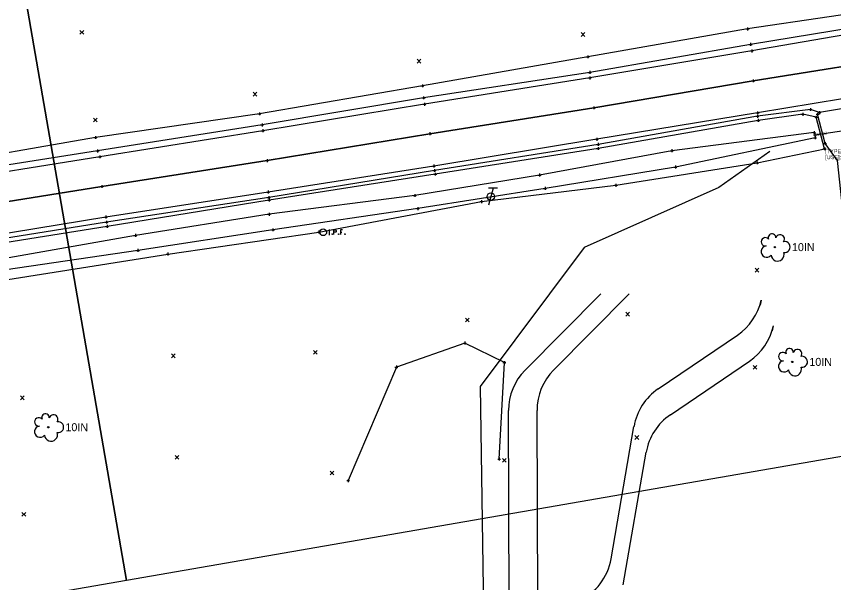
# Model space of a CAD drawing. Extents: x 1386013 to 1389776, y 604170 to 607009.
# Drawn here: x 1386684 to 1386970, y 604555.1 to 604753.1 of the extents above; entities that cross this region are included whole.
import ezdxf

# ---------------------------------------------------------------- set-up
doc = ezdxf.new("R2010")
doc.units = 0
for name, color, linetype in [('_CIVIL_CONSTRUCTION', 7, 'Continuous'), ('DR_X_Storm_Sewer', 7, 'Continuous'), ('DV_X_Text', 7, 'Continuous'), ('PM_X_CL_Double_Solid', 7, 'Continuous'), ('PV_X_COP', 7, 'Continuous'), ('PV_X_Driveway', 7, 'Continuous'), ('PV_X_EOP', 7, 'Continuous'), ('PV_X_Shoulder', 7, 'Continuous'), ('SC_Scratch1', 7, 'Continuous'), ('SH_Cut_Line', 7, 'Continuous'), ('SV_X_Random_Point', 7, 'Continuous'), ('SV_X_Text', 7, 'Continuous'), ('SV_X_Toe_of_Slope', 7, 'Continuous'), ('SV_X_Top_of_Bank', 7, 'Continuous'), ('UT_X_Leach_Bed', 7, 'Continuous'), ('UT_X_Telecom_Cells', 7, 'Continuous'), ('VG_X_Text', 7, 'Continuous'), ('VG_X_Tree_Line_Rt', 7, 'Continuous')]:
    doc.layers.add(name, color=color, linetype=linetype)

msp = doc.modelspace()

# ---------------------------------------------------------------- linework, layer by layer
at = {"layer": '_CIVIL_CONSTRUCTION'}
for centre in [(1386949.46, 604672.43), (1386955.54, 604632.3), (1386695.17, 604609.45)]:
    msp.add_circle(centre, 0.24, dxfattribs=at)
for centre, radius, start, end in [((1386946.15, 604674.29), 1.47, 39.0625, 279.5412), ((1386948.48, 604675.79), 1.32, 354.0047, 205.9741), ((1386951.29, 604675.25), 1.55, 323.83, 165.0376), ((1386946.61, 604670.88), 1.97, 96.1722, 320.5737), ((1386952.92, 604672.46), 1.91, 259.1453, 101.4596), ((1386950.41, 604669.82), 2.28, 184.9476, 19.4572), ((1386952.23, 604634.16), 1.47, 39.0625, 279.5412), ((1386954.56, 604635.67), 1.32, 354.0047, 205.9741), ((1386957.37, 604635.13), 1.55, 323.83, 165.0376), ((1386952.69, 604630.75), 1.97, 96.1722, 320.5737), ((1386959, 604632.34), 1.91, 259.1453, 101.4596), ((1386956.49, 604629.69), 2.28, 184.9476, 19.4572), ((1386691.86, 604611.31), 1.47, 39.0625, 279.5412), ((1386694.19, 604612.82), 1.32, 354.0047, 205.9741), ((1386697, 604612.28), 1.55, 323.83, 165.0376), ((1386692.32, 604607.9), 1.97, 96.1722, 320.5737), ((1386698.63, 604609.48), 1.91, 259.1453, 101.4596), ((1386696.12, 604606.84), 2.28, 184.9476, 19.4572)]:
    msp.add_arc(centre, radius, start, end, dxfattribs=at)
at = {"layer": 'DR_X_Storm_Sewer'}
msp.add_line((1386963.45, 604711.66), (1386994.09, 604716.38), dxfattribs=at)
msp.add_lwpolyline([(1386947.76, 604705.84), (1386929.86, 604693.24), (1386882.71, 604672.27), (1386846.3, 604623.65), (1386848.33, 604490.41), (1386873.09, 604380.23)], dxfattribs=at)
at = {"layer": 'DV_X_Text'}
for p, q in [((1386939.93, 604749.23), (1386939.93, 604748.23)), ((1386939.43, 604748.73), (1386940.43, 604748.73)), ((1386939.93, 604748.73), (1386939.93, 604748.73)), ((1386940.47, 604743.32), (1386941.47, 604743.32)), ((1386940.97, 604743.82), (1386940.97, 604742.82)), ((1386940.97, 604743.32), (1386940.97, 604743.32)), ((1386940.91, 604741.04), (1386941.91, 604741.04)), ((1386941.41, 604741.54), (1386941.41, 604740.54)), ((1386941.41, 604741.04), (1386941.41, 604741.04)), ((1386883.48, 604739), (1386884.48, 604739)), ((1386883.98, 604739.5), (1386883.98, 604738.5)), ((1386883.98, 604739), (1386883.98, 604739)), ((1386884.15, 604733.55), (1386885.15, 604733.55)), ((1386884.65, 604734.05), (1386884.65, 604733.05)), ((1386884.65, 604733.55), (1386884.65, 604733.55)), ((1386884.67, 604732.09), (1386884.67, 604731.09)), ((1386825.59, 604728.82), (1386826.59, 604728.82)), ((1386826.09, 604729.32), (1386826.09, 604728.32)), ((1386826.09, 604728.82), (1386826.09, 604728.82)), ((1386884.17, 604731.59), (1386885.17, 604731.59)), ((1386884.67, 604731.59), (1386884.67, 604731.59)), ((1386941.42, 604730.57), (1386942.42, 604730.57)), ((1386941.92, 604731.07), (1386941.92, 604730.07)), ((1386941.92, 604730.57), (1386941.92, 604730.57)), ((1386826.04, 604724.64), (1386827.04, 604724.64)), ((1386826.54, 604725.14), (1386826.54, 604724.14)), ((1386826.54, 604724.64), (1386826.54, 604724.64)), ((1386826.32, 604722.39), (1386827.32, 604722.39)), ((1386826.82, 604722.89), (1386826.82, 604721.89)), ((1386826.82, 604722.39), (1386826.82, 604722.39)), ((1386885.6, 604721.12), (1386886.6, 604721.12)), ((1386886.1, 604721.62), (1386886.1, 604720.62)), ((1386886.1, 604721.12), (1386886.1, 604721.12)), ((1386961.4, 604720.55), (1386962.4, 604720.55)), ((1386961.9, 604721.05), (1386961.9, 604720.05)), ((1386961.9, 604720.55), (1386961.9, 604720.55)), ((1386768.54, 604719.03), (1386769.54, 604719.03)), ((1386769.04, 604719.53), (1386769.04, 604718.53)), ((1386769.04, 604719.03), (1386769.04, 604719.03)), ((1386942.88, 604718.17), (1386943.88, 604718.17)), ((1386942.92, 604719.4), (1386943.92, 604719.4)), ((1386943.38, 604718.67), (1386943.38, 604717.67)), ((1386943.38, 604718.17), (1386943.38, 604718.17)), ((1386943.42, 604719.9), (1386943.42, 604718.9)), ((1386943.42, 604719.4), (1386943.42, 604719.4)), ((1386958.71, 604718.9), (1386959.71, 604718.9)), ((1386959.21, 604719.4), (1386959.21, 604718.4)), ((1386959.21, 604718.9), (1386959.21, 604718.9)), ((1386963.45, 604717.89), (1386964.45, 604717.89)), ((1386963.92, 604718.9), (1386964.92, 604718.9)), ((1386963.95, 604718.39), (1386963.95, 604717.39)), ((1386963.95, 604717.89), (1386963.95, 604717.89)), ((1386964.42, 604719.4), (1386964.42, 604718.4)), ((1386964.42, 604718.9), (1386964.42, 604718.9)), ((1386964.61, 604719.46), (1386965.61, 604719.46)), ((1386965.11, 604719.96), (1386965.11, 604718.96)), ((1386965.11, 604719.46), (1386965.11, 604719.46)), ((1386769.48, 604715.15), (1386770.48, 604715.15)), ((1386769.98, 604715.65), (1386769.98, 604714.65)), ((1386769.98, 604715.15), (1386769.98, 604715.15)), ((1386943.17, 604716.74), (1386944.17, 604716.74)), ((1386943.67, 604717.24), (1386943.67, 604716.24)), ((1386943.67, 604716.74), (1386943.67, 604716.74)), ((1386769.7, 604713.13), (1386770.7, 604713.13)), ((1386770.2, 604713.63), (1386770.2, 604712.63)), ((1386770.2, 604713.13), (1386770.2, 604713.13)), ((1386828.25, 604712.1), (1386829.25, 604712.1)), ((1386828.75, 604712.6), (1386828.75, 604711.6)), ((1386828.75, 604712.1), (1386828.75, 604712.1)), ((1386962.7, 604712.53), (1386963.7, 604712.53)), ((1386962.95, 604711.66), (1386963.95, 604711.66)), ((1386963.2, 604713.03), (1386963.2, 604712.03)), ((1386963.2, 604712.53), (1386963.2, 604712.53)), ((1386963.45, 604712.16), (1386963.45, 604711.16)), ((1386963.45, 604711.66), (1386963.45, 604711.66)), ((1386711.2, 604710.77), (1386712.2, 604710.77)), ((1386711.7, 604711.27), (1386711.7, 604710.27)), ((1386711.7, 604710.77), (1386711.7, 604710.77)), ((1386886.64, 604710.13), (1386887.64, 604710.13)), ((1386887.14, 604710.63), (1386887.14, 604709.63)), ((1386887.14, 604710.13), (1386887.14, 604710.13)), ((1386887.62, 604708.86), (1386887.62, 604707.86)), ((1386963.06, 604710.65), (1386964.06, 604710.65)), ((1386963.56, 604711.15), (1386963.56, 604710.15)), ((1386963.56, 604710.65), (1386963.56, 604710.65)), ((1386967.09, 604709.18), (1386967.09, 604708.18)), ((1386711.92, 604706.07), (1386712.92, 604706.07)), ((1386712.42, 604706.57), (1386712.42, 604705.57)), ((1386712.42, 604706.07), (1386712.42, 604706.07)), ((1386887.08, 604706.91), (1386888.08, 604706.91)), ((1386887.12, 604708.36), (1386888.12, 604708.36)), ((1386887.58, 604707.41), (1386887.58, 604706.41)), ((1386887.58, 604706.91), (1386887.58, 604706.91)), ((1386887.62, 604708.36), (1386887.62, 604708.36)), ((1386912.92, 604706.16), (1386913.92, 604706.16)), ((1386913.42, 604706.66), (1386913.42, 604705.66)), ((1386913.42, 604706.16), (1386913.42, 604706.16)), ((1386966.3, 604706.78), (1386967.3, 604706.78)), ((1386966.45, 604706.82), (1386967.45, 604706.82)), ((1386966.59, 604708.68), (1386967.59, 604708.68)), ((1386966.8, 604707.28), (1386966.8, 604706.28)), ((1386966.8, 604706.78), (1386966.8, 604706.78)), ((1386966.95, 604707.32), (1386966.95, 604706.32)), ((1386966.95, 604706.82), (1386966.95, 604706.82)), ((1386967.09, 604708.68), (1386967.09, 604708.68)), ((1386712.65, 604704.01), (1386713.65, 604704.01)), ((1386713.15, 604704.51), (1386713.15, 604703.51)), ((1386713.15, 604704.01), (1386713.15, 604704.01)), ((1386771.72, 604703.17), (1386771.72, 604702.17)), ((1386771.22, 604702.67), (1386772.22, 604702.67)), ((1386771.72, 604702.67), (1386771.72, 604702.67)), ((1386829.62, 604700.78), (1386830.62, 604700.78)), ((1386830.12, 604701.28), (1386830.12, 604700.28)), ((1386830.12, 604700.78), (1386830.12, 604700.78)), ((1386914.19, 604700.42), (1386915.19, 604700.42)), ((1386914.69, 604700.92), (1386914.69, 604699.92)), ((1386914.69, 604700.42), (1386914.69, 604700.42)), ((1386942.8, 604701.92), (1386943.8, 604701.92)), ((1386943.3, 604702.42), (1386943.3, 604701.42)), ((1386943.3, 604701.92), (1386943.3, 604701.92)), ((1386829.86, 604699.21), (1386830.86, 604699.21)), ((1386830.11, 604697.95), (1386831.11, 604697.95)), ((1386830.36, 604699.71), (1386830.36, 604698.71)), ((1386830.36, 604699.21), (1386830.36, 604699.21)), ((1386830.61, 604698.45), (1386830.61, 604697.45)), ((1386830.61, 604697.95), (1386830.61, 604697.95)), ((1386866.62, 604697.62), (1386867.62, 604697.62)), ((1386867.12, 604698.12), (1386867.12, 604697.12)), ((1386867.12, 604697.62), (1386867.12, 604697.62)), ((1386893.85, 604694.55), (1386893.85, 604693.55)), ((1386713.35, 604693.61), (1386714.35, 604693.61)), ((1386713.85, 604694.11), (1386713.85, 604693.11)), ((1386713.85, 604693.61), (1386713.85, 604693.61)), ((1386771.6, 604691.69), (1386772.6, 604691.69)), ((1386772.1, 604692.19), (1386772.1, 604691.19)), ((1386772.1, 604691.69), (1386772.1, 604691.69)), ((1386868.52, 604692.96), (1386869.52, 604692.96)), ((1386869.02, 604693.46), (1386869.02, 604692.46)), ((1386869.02, 604692.96), (1386869.02, 604692.96)), ((1386893.35, 604694.05), (1386894.35, 604694.05)), ((1386893.85, 604694.05), (1386893.85, 604694.05)), ((1386771.8, 604689.74), (1386772.8, 604689.74)), ((1386771.95, 604688.91), (1386772.95, 604688.91)), ((1386772.3, 604690.24), (1386772.3, 604689.24)), ((1386772.3, 604689.74), (1386772.3, 604689.74)), ((1386772.45, 604689.41), (1386772.45, 604688.41)), ((1386772.45, 604688.91), (1386772.45, 604688.91)), ((1386822.92, 604690.47), (1386823.92, 604690.47)), ((1386823.42, 604690.97), (1386823.42, 604689.97)), ((1386823.42, 604690.47), (1386823.42, 604690.47)), ((1386846.74, 604688.83), (1386846.74, 604687.83)), ((1386824, 604685.91), (1386825, 604685.91)), ((1386824.5, 604686.41), (1386824.5, 604685.41)), ((1386824.5, 604685.91), (1386824.5, 604685.91)), ((1386846.24, 604688.33), (1386847.24, 604688.33)), ((1386846.74, 604688.33), (1386846.74, 604688.33)), ((1386715.3, 604683.44), (1386715.3, 604682.44)), ((1386771.94, 604683.92), (1386772.94, 604683.92)), ((1386772.44, 604684.42), (1386772.44, 604683.42)), ((1386772.44, 604683.92), (1386772.44, 604683.92)), ((1386714.8, 604682.94), (1386715.8, 604682.94)), ((1386715.06, 604681.18), (1386716.06, 604681.18)), ((1386715.3, 604682.94), (1386715.3, 604682.94)), ((1386715.56, 604681.68), (1386715.56, 604680.68)), ((1386715.56, 604681.18), (1386715.56, 604681.18)), ((1386715.75, 604680.2), (1386715.75, 604679.2)), ((1386715.25, 604679.7), (1386716.25, 604679.7)), ((1386715.75, 604679.7), (1386715.75, 604679.7)), ((1386773.31, 604678.46), (1386774.31, 604678.46)), ((1386773.81, 604678.96), (1386773.81, 604677.96)), ((1386773.81, 604678.46), (1386773.81, 604678.46)), ((1386789.41, 604677.7), (1386790.41, 604677.7)), ((1386789.91, 604678.2), (1386789.91, 604677.2)), ((1386789.91, 604677.7), (1386789.91, 604677.7)), ((1386725.14, 604676.53), (1386726.14, 604676.53)), ((1386725.64, 604677.03), (1386725.64, 604676.03)), ((1386725.64, 604676.53), (1386725.64, 604676.53)), ((1386726.54, 604671.79), (1386726.54, 604670.79)), ((1386726.04, 604671.29), (1386727.04, 604671.29)), ((1386726.54, 604671.29), (1386726.54, 604671.29)), ((1386736.47, 604670), (1386737.47, 604670)), ((1386736.97, 604670.5), (1386736.97, 604669.5)), ((1386736.97, 604670), (1386736.97, 604670)), ((1386840.47, 604638.87), (1386841.47, 604638.87)), ((1386840.97, 604639.37), (1386840.97, 604638.37)), ((1386840.97, 604638.87), (1386840.97, 604638.87)), ((1386854.3, 604632.1), (1386855.3, 604632.1)), ((1386854.8, 604632.6), (1386854.8, 604631.6)), ((1386854.8, 604632.1), (1386854.8, 604632.1)), ((1386816.49, 604630.49), (1386817.49, 604630.49)), ((1386816.99, 604630.99), (1386816.99, 604629.99)), ((1386816.99, 604630.49), (1386816.99, 604630.49)), ((1386852.49, 604598.32), (1386853.49, 604598.32)), ((1386852.99, 604598.82), (1386852.99, 604597.82)), ((1386852.99, 604598.32), (1386852.99, 604598.32)), ((1386799.64, 604590.78), (1386800.64, 604590.78)), ((1386800.14, 604591.28), (1386800.14, 604590.28)), ((1386800.14, 604590.78), (1386800.14, 604590.78))]:
    msp.add_line(p, q, dxfattribs=at)
at = {"layer": 'PM_X_CL_Double_Solid'}
msp.add_lwpolyline([(1386468.73, 604654.2), (1386537.3, 604664.92), (1386594.48, 604674.79), (1386656.33, 604684.46), (1386713.85, 604693.61), (1386771.72, 604702.67), (1386828.75, 604712.1), (1386886.1, 604721.12), (1386941.92, 604730.57), (1387000.37, 604739.9)], dxfattribs=at)
at = {"layer": 'PV_X_COP'}
msp.add_lwpolyline([(1387000.37, 604739.9), (1386941.92, 604730.57), (1386886.1, 604721.12), (1386828.75, 604712.1), (1386771.72, 604702.67), (1386713.85, 604693.61), (1386656.33, 604684.46), (1386594.48, 604674.79), (1386537.3, 604664.92), (1386475.24, 604654.93), (1386414.35, 604644.79), (1386366.58, 604636.8), (1386295.22, 604625.24), (1386269.2, 604620.76)], dxfattribs=at)
at = {"layer": 'PV_X_Driveway'}
msp.add_lwpolyline([(1386976.17, 604633.16), (1386974.25, 604675.51), (1386971.44, 604702.7), (1386967.09, 604708.68), (1386964.42, 604718.9)], dxfattribs=at)
at = {"layer": 'PV_X_EOP'}
for points in [[(1386999.09, 604750.97), (1386941.41, 604741.04), (1386884.67, 604731.59), (1386826.82, 604722.39), (1386770.2, 604713.13), (1386713.15, 604704.01), (1386654.93, 604694.71), (1386593.34, 604684.8), (1386535.41, 604675.21), (1386469.16, 604664.5), (1386392.09, 604651.62), (1386332.26, 604641.82), (1386267.39, 604631.1)], [(1387002.9, 604729.17), (1386943.42, 604719.4), (1386887.14, 604710.13), (1386830.12, 604700.78), (1386772.1, 604691.69), (1386715.3, 604682.94), (1386657.65, 604673.44), (1386596.41, 604663.71), (1386538.98, 604654.04), (1386477.51, 604644.07), (1386414.44, 604633.64), (1386368.83, 604626.04), (1386296.84, 604614.17), (1386270.69, 604609.87)]]:
    msp.add_lwpolyline(points, dxfattribs=at)
at = {"layer": 'PV_X_Shoulder'}
for points in [[(1386998.59, 604752.7), (1386940.97, 604743.32), (1386884.65, 604733.55), (1386826.54, 604724.64), (1386769.98, 604715.15), (1386712.42, 604706.07), (1386654.65, 604697.02), (1386593.22, 604686.44), (1386535.13, 604677.03), (1386468.95, 604665.92), (1386392.3, 604653.36), (1386331.76, 604643.52), (1386267.19, 604632.89)], [(1386985.4, 604722.84), (1386965.11, 604719.46), (1386961.9, 604720.55), (1386943.38, 604718.17), (1386887.62, 604708.36), (1386830.36, 604699.21), (1386772.3, 604689.74), (1386715.56, 604681.18), (1386657.89, 604671.95), (1386596.66, 604661.6), (1386577.12, 604657.52), (1386569.07, 604656.76), (1386539.67, 604652.01), (1386479.08, 604642.34), (1386478.07, 604642.14), (1386414.53, 604632.43), (1386369.38, 604624.9), (1386296.82, 604613.19), (1386270.73, 604608.85)]]:
    msp.add_lwpolyline(points, dxfattribs=at)
at = {"layer": 'SC_Scratch1'}
for points in [[(1386793.4, 604678.44), (1386793.75, 604678.44)], [(1386793.57, 604676.84), (1386793.57, 604678.44)], [(1386795.14, 604676.84), (1386795.14, 604678.44), (1386795.67, 604678.44), (1386795.72, 604678.43), (1386795.8, 604678.4), (1386795.83, 604678.38), (1386795.86, 604678.35), (1386795.91, 604678.29), (1386795.94, 604678.22), (1386795.96, 604678.12), (1386795.96, 604677.97), (1386795.95, 604677.92), (1386795.93, 604677.85), (1386795.89, 604677.76), (1386795.84, 604677.72), (1386795.81, 604677.69), (1386795.75, 604677.67), (1386795.67, 604677.66), (1386795.14, 604677.66)], [(1386798.15, 604678.44), (1386797.39, 604678.44), (1386797.39, 604676.84)], [(1386797.39, 604677.66), (1386797.93, 604677.66)], [(1386793.4, 604676.84), (1386793.75, 604676.84)], [(1386794.53, 604677.05), (1386794.59, 604677.05), (1386794.62, 604677.03), (1386794.65, 604676.98), (1386794.65, 604676.91), (1386794.62, 604676.86), (1386794.59, 604676.84), (1386794.53, 604676.84), (1386794.5, 604676.86), (1386794.46, 604676.91), (1386794.46, 604676.98), (1386794.5, 604677.03), (1386794.53, 604677.05)], [(1386796.78, 604677.05), (1386796.83, 604677.05), (1386796.87, 604677.03), (1386796.9, 604676.98), (1386796.9, 604676.91), (1386796.87, 604676.86), (1386796.83, 604676.84), (1386796.78, 604676.84), (1386796.75, 604676.86), (1386796.71, 604676.91), (1386796.71, 604676.98), (1386796.75, 604677.03), (1386796.78, 604677.05)], [(1386798.93, 604677.05), (1386798.98, 604677.05), (1386799.02, 604677.03), (1386799.05, 604676.98), (1386799.05, 604676.91), (1386799.02, 604676.86), (1386798.98, 604676.84), (1386798.93, 604676.84), (1386798.9, 604676.86), (1386798.86, 604676.91), (1386798.86, 604676.98), (1386798.9, 604677.03), (1386798.93, 604677.05)]]:
    msp.add_lwpolyline(points, dxfattribs=at)
msp.add_circle((1386791.38, 604677.64), 1.2, dxfattribs=at)
at = {"layer": 'SH_Cut_Line'}
for points in [[(1386722.57, 604555.82), (1386685.02, 604772.59), (1387020.03, 604830.63), (1387057.58, 604613.85)], [(1386387.56, 604497.79), (1386350, 604714.56), (1386685.02, 604772.59), (1386722.57, 604555.82)]]:
    msp.add_lwpolyline(points, close=True, dxfattribs=at)
at = {"layer": 'SV_X_Random_Point'}
for p, q in [((1386706.26, 604746.88), (1386707.59, 604748.22)), ((1386706.26, 604748.22), (1386707.59, 604746.88)), ((1386881.67, 604746.09), (1386883, 604747.43)), ((1386881.67, 604747.43), (1386883, 604746.09)), ((1386824.23, 604736.82), (1386825.57, 604738.15)), ((1386824.23, 604738.15), (1386825.57, 604736.82)), ((1386766.88, 604725.27), (1386768.21, 604726.6)), ((1386766.88, 604726.6), (1386768.21, 604725.27)), ((1386710.95, 604716.23), (1386712.28, 604717.56)), ((1386710.95, 604717.56), (1386712.28, 604716.23)), ((1386942.58, 604663.73), (1386943.91, 604665.06)), ((1386942.58, 604665.06), (1386943.91, 604663.73)), ((1386897.28, 604648.31), (1386898.61, 604649.64)), ((1386897.28, 604649.64), (1386898.61, 604648.31)), ((1386841.17, 604646.31), (1386842.5, 604647.64)), ((1386841.17, 604647.64), (1386842.5, 604646.31)), ((1386738.3, 604633.77), (1386739.63, 604635.1)), ((1386738.3, 604635.1), (1386739.63, 604633.77)), ((1386787.94, 604635), (1386789.27, 604636.33)), ((1386787.94, 604636.33), (1386789.27, 604635)), ((1386941.82, 604629.74), (1386943.15, 604631.08)), ((1386941.82, 604631.08), (1386943.15, 604629.74)), ((1386685.44, 604619.05), (1386686.77, 604620.39)), ((1386685.44, 604620.39), (1386686.77, 604619.05)), ((1386900.47, 604605.19), (1386901.8, 604606.53)), ((1386900.47, 604606.53), (1386901.8, 604605.19)), ((1386739.58, 604598.25), (1386740.91, 604599.58)), ((1386739.58, 604599.58), (1386740.91, 604598.25)), ((1386854.1, 604597.19), (1386855.43, 604598.53)), ((1386854.1, 604598.53), (1386855.43, 604597.19)), ((1386793.78, 604592.79), (1386795.11, 604594.12)), ((1386793.78, 604594.12), (1386795.11, 604592.79)), ((1386685.93, 604578.32), (1386687.26, 604579.65)), ((1386685.93, 604579.65), (1386687.26, 604578.32))]:
    msp.add_line(p, q, dxfattribs=at)
at = {"layer": 'SV_X_Toe_of_Slope'}
for points in [[(1387571.9, 604860.13), (1387513.17, 604847.9), (1387455.73, 604837.69), (1387401.04, 604827.65), (1387339.29, 604815.83), (1387289.1, 604807.74), (1387230.03, 604798.15), (1387173.08, 604787.71), (1387123.84, 604780.19), (1387058.58, 604768.72), (1386997.09, 604757.11), (1386939.93, 604748.73), (1386883.98, 604739), (1386826.09, 604728.82), (1386769.04, 604719.03), (1386711.7, 604710.77), (1386654.03, 604700.72), (1386592.6, 604690.63), (1386534.1, 604681.18), (1386480.03, 604672.89), (1386465.51, 604671.66), (1386391.46, 604656.56), (1386330.8, 604647.36), (1386266.18, 604637.16)], [(1386963.2, 604712.53), (1386913.42, 604706.16), (1386867.12, 604697.62), (1386823.42, 604690.47), (1386772.44, 604683.92), (1386725.64, 604676.53), (1386679.38, 604668.33), (1386624.7, 604659.25), (1386582.26, 604652.52), (1386568.55, 604650.6)], [(1386963.56, 604710.65), (1386914.69, 604700.42), (1386869.02, 604692.96), (1386824.5, 604685.91), (1386773.81, 604678.46), (1386726.54, 604671.29), (1386680.47, 604664.52), (1386626.57, 604654.95), (1386583.16, 604648.99), (1386569.14, 604647.05)]]:
    msp.add_lwpolyline(points, dxfattribs=at)
at = {"layer": 'SV_X_Top_of_Bank'}
for points in [[(1386966.8, 604706.78), (1386963.95, 604717.89), (1386959.21, 604718.9), (1386943.67, 604716.74), (1386887.58, 604706.91), (1386830.61, 604697.95), (1386772.45, 604688.91), (1386715.75, 604679.7), (1386657.87, 604670.42), (1386596.85, 604660.69), (1386577.49, 604656.95), (1386569.73, 604656.09), (1386567.9, 604652.78)], [(1386569.34, 604643.85), (1386624.92, 604650.78), (1386681.01, 604661.09), (1386736.97, 604670), (1386789.91, 604677.7), (1386846.74, 604688.33), (1386893.85, 604694.05), (1386943.3, 604701.92), (1386966.95, 604706.82)]]:
    msp.add_lwpolyline(points, dxfattribs=at)
at = {"layer": 'UT_X_Leach_Bed'}
for p, q in [((1386862.03, 604629.42), (1386888.5, 604656.09)), ((1386872.03, 604629.46), (1386898.5, 604656.13)), ((1386944.67, 604653.92), (1386944.3, 604652.18)), ((1386948.93, 604644.87), (1386948.56, 604643.13)), ((1386908.66, 604622.86), (1386936.34, 604641.6)), ((1386912.92, 604613.82), (1386940.6, 604632.56)), ((1386856.59, 604523.54), (1386856.23, 604615.25)), ((1386866.59, 604523.58), (1386866.23, 604615.29)), ((1386892.12, 604563.43), (1386900.16, 604609.72)), ((1386896.38, 604554.38), (1386904.42, 604600.68))]:
    msp.add_line(p, q, dxfattribs=at)
for centre, start, end in [((1386925.13, 604658.17), 304.0943, 347.7483), ((1386929.39, 604649.12), 304.0943, 347.7483), ((1386876.23, 604615.33), 135.2238, 180.2238), ((1386886.23, 604615.37), 135.2238, 180.2238), ((1386919.87, 604606.3), 124.0943, 170.1475), ((1386924.13, 604597.25), 124.0943, 170.1475), ((1386872.42, 604566.85), 295.2097, 350.1475)]:
    msp.add_arc(centre, 20, start, end, dxfattribs=at)
at = {"layer": 'UT_X_Telecom_Cells'}
for p, q in [((1386850.84, 604693.09), (1386849.23, 604687.09)), ((1386852.44, 604693.09), (1386849.24, 604693.09))]:
    msp.add_line(p, q, dxfattribs=at)
msp.add_circle((1386850.04, 604690.09), 1.3, dxfattribs=at)
at = {"layer": 'VG_X_Tree_Line_Rt'}
msp.add_lwpolyline([(1386852.99, 604598.32), (1386854.8, 604632.1), (1386840.97, 604638.87), (1386816.99, 604630.49), (1386800.14, 604590.78)], dxfattribs=at)

# ---------------------------------------------------------------- texts
at = {"layer": 'SC_Scratch1'}
msp.add_text("916.56'", height=1, rotation=8.7463, dxfattribs=at).set_placement((1386963.53, 604711.17))
at = {"layer": 'SV_X_Text'}
for s, p in [('[TYPE]:Stone', (1386967.09, 604705.28)), ('[USE]:Residential', (1386967.09, 604703.18))]:
    msp.add_text(s, height=1.4, dxfattribs=at).set_placement(p)
at = {"layer": 'VG_X_Text'}
for p in [(1386955.46, 604671.03), (1386961.54, 604630.9), (1386701.17, 604608.05)]:
    msp.add_text('10IN', height=2.8, dxfattribs=at).set_placement(p)

doc.saveas('drawing.dxf')
